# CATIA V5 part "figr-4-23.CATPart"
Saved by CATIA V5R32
Part number: Part1
Bounding box of the stored display mesh (mm): x 0 to 79, y -70 to 90, z -90 to 70
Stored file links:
  D:\PROJECTS\Project 2022\CATIA V5 6R 2022\Resources\Part Files\c04_catia_v5_6r2022_prt\figr-4-23.CATPart
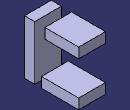
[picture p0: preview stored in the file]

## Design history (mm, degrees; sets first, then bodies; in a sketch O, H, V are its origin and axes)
Body1 (main body)
  Sketch1 on yz-plane, origin (0, 0, 0), H (0, 1, 0), V (0, 0, 1)
    line L1 (-100, 100) -> (100, 100)
    line L2 (100, 100) -> (100, -100)
    line L3 (100, -100) -> (-100, -100)
    line L4 (-100, -100) -> (-100, 100)
    line L5 (-70, 70) -> (-40, 70)
    line L6 (-40, 70) -> (-40, -90)
    line L7 (-40, -90) -> (-70, -90)
    line L8 (-70, -90) -> (-70, 70)
    line L9 (-10, 70) -> (90, 70)
    line L10 (90, 70) -> (90, 40)
    line L11 (90, 40) -> (-10, 40)
    line L12 (-10, 40) -> (-10, 70)
    point P13 (90, -90)
    line L13 (90, -90) -> (-20, -90)
    line L14 (-20, -90) -> (-20, -60)
    line L15 (-20, -60) -> (90, -60)
    line L16 (90, -60) -> (90, -90)
    horizontal: L1 H, L3 H, L5 H, L7 H, L9 H, L11 H, L13 H, L15 H
    vertical: L2 V, L4 V, L6 V, L8 V, L10 V, L12 V, L14 V, L16 V
    coincidence: P13 L10, P13 L7
  Pad1: profile edge of Sketch1, length 79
